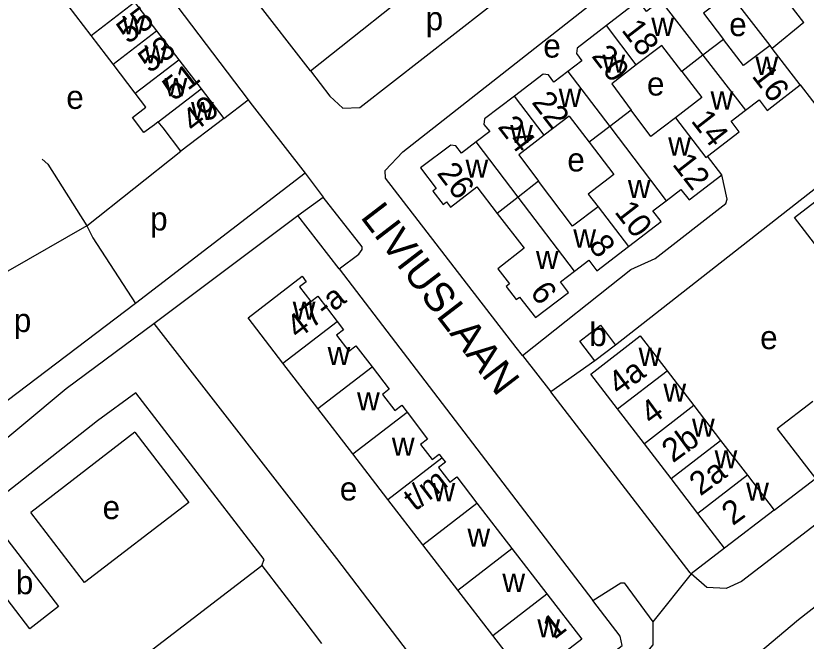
# Model space of a CAD drawing. Extents: x 158848 to 160613, y 385889 to 387762.
# Drawn here: x 159871.5 to 160005.9, y 386555.9 to 386662.2 of the extents above; entities that cross this region are included whole.
import ezdxf

# ---------------------------------------------------------------- set-up
doc = ezdxf.new("R2010")
doc.units = 0
for name, color, linetype in [('BLT_Basislijn', 7, 'Continuous'), ('BLT_Bebouwing', 7, 'Continuous'), ('BLT_Centroide', 7, 'Continuous'), ('BLT_Huisnummer', 7, 'Continuous'), ('BLT_Huisnummer_ tussenligend', 7, 'Continuous'), ('BLT_Huisnummer_reeks', 7, 'Continuous'), ('BLT_Onderverdeling_panden', 7, 'Continuous'), ('BLT_Straatnaam', 7, 'Continuous'), ('BLT_Vlakafsluiter', 7, 'Continuous')]:
    doc.layers.add(name, color=color, linetype=linetype)

msp = doc.modelspace()

# ---------------------------------------------------------------- linework, layer by layer
at = {"layer": 'BLT_Basislijn'}
for p, q in [((159884.03, 386683.48), (159911, 386647.86)), ((160005.44, 386661.04), (159990.37, 386680.7)), ((159921.59, 386652.82), (159906.39, 386672.41)), ((159999.71, 386657.09), (159992.86, 386666.02)), ((160005.44, 386661.04), (160000.09, 386656.59)), ((160004.85, 386650.41), (160014.24, 386638.14)), ((159906.88, 386644.73), (159911, 386647.86)), ((159883.58, 386626.46), (159899.58, 386639.13)), ((159920.72, 386635.41), (159891.89, 386613.25)), ((159920.72, 386635.41), (159923.79, 386631.33)), ((159919.47, 386628.21), (159923.79, 386631.33)), ((159895, 386609.89), (159919.47, 386628.21)), ((159926.49, 386619.16), (159919.47, 386628.21)), ((159883.58, 386626.46), (159870.14, 386618.76)), ((159926.49, 386619.16), (159969.61, 386562.76)), ((159891.89, 386613.25), (159865.31, 386593.16)), ((159957.66, 386604.4), (159962.44, 386598.28)), ((159891.74, 386591.41), (159874.1, 386577.74)), ((159891.74, 386591.41), (159900.93, 386579.45)), ((160000.42, 386578.15), (160007.45, 386583.53)), ((159900.93, 386579.45), (159883.22, 386565.85)), ((159883.22, 386565.85), (159874.1, 386577.74)), ((159992, 386571.67), (159986.32, 386567.3))]:
    msp.add_line(p, q, dxfattribs=at)
for points in [[(159921.59, 386652.82), (159942.74, 386669.61), (159958.92, 386681.91)], [(159921.59, 386652.82), (159924.88, 386648.51), (159927.11, 386646.48), (159929.97, 386646.58), (159962.27, 386671.77), (159963.06, 386672.72), (159963.34, 386675), (159963.14, 386675.85), (159961.74, 386678.2), (159958.92, 386681.91)], [(159957.66, 386604.4), (159956.57, 386605.79), (159953.09, 386610.25), (159934.35, 386634.59), (159934.32, 386635.86), (159937.29, 386639.04), (159985.85, 386677.21), (159990.37, 386680.7)], [(159911, 386647.86), (159911.3, 386647.47), (159920.72, 386635.41)], [(159876.02, 386637.8), (159876.95, 386636.94), (159883.58, 386626.46)], [(160014.24, 386638.14), (159973.45, 386606.21)], [(159957.66, 386604.4), (159976.06, 386619.05), (159980.18, 386620.91), (159992.19, 386630.25), (159992.43, 386630.99), (159991.54, 386635.15)], [(159926.49, 386619.16), (159929.8, 386621.67), (159930.39, 386622.43), (159930.39, 386622.91), (159923.79, 386631.33)], [(159883.58, 386626.46), (159884.61, 386624.45), (159891.89, 386613.25)], [(160072, 386625.2), (159994.85, 386566.02), (159992.27, 386564.83), (159988.99, 386564.97), (159986.32, 386567.3)], [(159816.01, 386559.58), (159856.57, 386580.44), (159864.97, 386586.23), (159880.09, 386598.8), (159895, 386609.89)], [(159895, 386609.89), (159926.03, 386569.94), (159951.15, 386537.01)], [(159969.95, 386603.52), (159962.44, 386598.28)], [(159913.33, 386568.72), (159913.75, 386569.78), (159891.93, 386598.06), (159885.42, 386593.32), (159833.17, 386552.18), (159833.33, 386550.75), (159852.66, 386513.61), (159854.09, 386514), (159867.93, 386521.11)], [(159986.32, 386567.3), (159986.12, 386567.48), (159962.44, 386598.28)], [(160049.48, 386583.96), (160045.31, 386588.46), (160043.15, 386588.7), (160039.17, 386586.55), (160004.57, 386559.51), (159997.74, 386553.78), (159997.8, 386551.51), (160003.17, 386544.41)], [(159969.61, 386562.76), (159974.36, 386565.79), (159974.9, 386565.77), (159979.77, 386559.18)], [(159951.15, 386537.01), (159974.56, 386555.12), (159974.26, 386556.7), (159969.61, 386562.76)], [(159979.77, 386559.18), (159979.77, 386555.27), (159977.95, 386553.04), (159925.28, 386512.85), (159863.76, 386464.98), (159852.68, 386456.75)]]:
    msp.add_lwpolyline(points, dxfattribs=at)
at = {"layer": 'BLT_Bebouwing'}
for p, q in [((159891.71, 386664.5), (159895.45, 386659.62)), ((159895.45, 386659.62), (159899.23, 386654.69)), ((160000.09, 386656.59), (159999.71, 386657.09)), ((160004.85, 386650.41), (160000.09, 386656.59)), ((159899.23, 386654.69), (159903.02, 386649.75)), ((159903.02, 386649.75), (159906.88, 386644.73)), ((159906.88, 386644.73), (159899.58, 386639.13)), ((159965.6, 386645.08), (159961.35, 386641.85)), ((159965.6, 386645.08), (159968.97, 386640.66)), ((159991.54, 386635.15), (159989.1, 386638.31)), ((159973.45, 386606.21), (159969.95, 386603.52)), ((159922.88, 386595.41), (159916.93, 386603.13)), ((159982.21, 386601.82), (159986.77, 386595.91)), ((159928.82, 386587.7), (159922.88, 386595.41)), ((159978.35, 386589.43), (159973.79, 386595.34)), ((159986.77, 386595.91), (159991.32, 386589.99)), ((159982.9, 386583.51), (159978.35, 386589.43)), ((159991.32, 386589.99), (159995.87, 386584.07)), ((159934.76, 386579.98), (159928.82, 386587.7)), ((159987.45, 386577.59), (159982.9, 386583.51)), ((159940.71, 386572.27), (159934.76, 386579.98)), ((159949.9, 386579.35), (159955.85, 386571.64)), ((159946.65, 386564.55), (159940.71, 386572.27)), ((159955.85, 386571.64), (159961.79, 386563.92)), ((159888.9, 386550.01), (159913.33, 386568.72)), ((159952.59, 386556.84), (159946.65, 386564.55))]:
    msp.add_line(p, q, dxfattribs=at)
for points in [[(159992.86, 386666.02), (159988.38, 386662.59), (159991.78, 386658.14)], [(159981.09, 386664.77), (159978.7, 386662.91), (159977.74, 386664.17), (159976.87, 386664.31), (159971.94, 386660.54)], [(159884.34, 386658.84), (159880.42, 386663.94)], [(159971.94, 386660.54), (159966.92, 386656.69), (159966.82, 386655.75), (159967.75, 386654.51), (159965.37, 386652.7)], [(159888.07, 386653.95), (159886.96, 386655.43), (159884.34, 386658.84)], [(159999.71, 386657.09), (159995.19, 386653.69), (159991.78, 386658.14)], [(159984.7, 386652.71), (159981.3, 386657.13), (159976.99, 386653.81)], [(159891.83, 386649.01), (159888.07, 386653.95)], [(159976.99, 386653.81), (159972.84, 386650.61), (159976.09, 386646.1)], [(159965.37, 386652.7), (159962.98, 386650.88), (159962.05, 386652.11), (159961.15, 386652.27), (159956.26, 386648.53)], [(159984.7, 386652.71), (159988.12, 386648.26), (159983.66, 386644.84)], [(159995.56, 386646.12), (159997.85, 386647.88), (159999.23, 386646.09), (160000, 386646.68), (160004.85, 386650.41)], [(159895.73, 386644.16), (159895.08, 386643.66), (159893.3, 386642.32), (159891.33, 386644.88), (159893.64, 386646.65), (159891.83, 386649.01)], [(159956.26, 386648.53), (159951.17, 386644.64), (159951.09, 386643.7), (159952.07, 386642.49), (159949.74, 386640.72)], [(159983.66, 386644.84), (159979.47, 386641.63), (159976.09, 386646.1)], [(159989.1, 386638.31), (159994.47, 386642.43), (159993.09, 386644.23), (159995.56, 386646.12)], [(159899.58, 386639.13), (159896.54, 386643.1), (159895.73, 386644.16)], [(159961.35, 386641.85), (159957.04, 386638.56), (159960.35, 386634.04)], [(159949.74, 386640.72), (159947.26, 386638.84), (159946.33, 386640.05), (159945.46, 386640.17), (159940.29, 386636.3), (159942.97, 386632.8), (159942.43, 386632.37), (159944.15, 386630.11), (159944.7, 386630.55), (159945.4, 386629.64), (159949.89, 386633.07), (159953.35, 386628.59)], [(159968.97, 386640.66), (159973.15, 386635.2), (159968.8, 386631.86), (159970.48, 386629.71)], [(159982.08, 386630.74), (159984.57, 386632.65), (159985.95, 386630.86), (159991.54, 386635.15)], [(159970.48, 386629.71), (159966.15, 386626.39), (159960.35, 386634.04)], [(160008.4, 386621.97), (160003.86, 386627.86), (160012.27, 386634.36), (160016.82, 386628.44)], [(159975.66, 386622.95), (159981.19, 386627.2), (159979.81, 386628.99), (159982.08, 386630.74)], [(159953.34, 386628.59), (159957.95, 386622.65), (159953.45, 386619.16), (159955.43, 386616.61), (159954.86, 386616.18), (159956.59, 386613.93), (159957.15, 386614.36), (159959.85, 386610.86), (159965.48, 386615.15), (159964.11, 386616.95), (159966.5, 386618.78)], [(159966.5, 386618.78), (159968.9, 386620.61), (159970.27, 386618.81), (159975.66, 386622.95)], [(159916.93, 386603.13), (159910.99, 386610.85), (159920.17, 386617.9), (159920.88, 386616.97), (159919.74, 386616.09), (159921.67, 386613.58), (159922.86, 386614.49), (159926.14, 386610.22)], [(159926.14, 386610.22), (159927.22, 386608.81), (159926.04, 386607.9), (159928.14, 386605.17), (159929.33, 386606.09), (159932.08, 386602.5)], [(159969.95, 386603.52), (159967.39, 386606.88), (159970.89, 386609.56), (159973.45, 386606.21)], [(159973.79, 386595.34), (159969.24, 386601.26), (159977.65, 386607.75), (159982.21, 386601.82)], [(159932.08, 386602.5), (159934.99, 386598.71), (159933.83, 386597.82), (159935.94, 386595.07), (159937.11, 386595.96), (159938.02, 386594.78)], [(160007, 386596.63), (160000.95, 386591.95), (160007.45, 386583.53)], [(159938.02, 386594.78), (159941.52, 386590.23), (159940.33, 386589.31), (159942.29, 386586.76), (159943.47, 386587.67), (159943.95, 386587.06)], [(159943.95, 386587.06), (159944.53, 386586.3), (159943.37, 386585.4), (159945.3, 386582.88), (159946.48, 386583.79), (159949.9, 386579.35)], [(159995.87, 386584.07), (160000.42, 386578.15)], [(159992, 386571.67), (159987.45, 386577.59)], [(160000.42, 386578.15), (159992, 386571.67)], [(159913.33, 386568.72), (159920.46, 386559.42), (159923.5, 386555.45)], [(159961.79, 386563.92), (159967.74, 386556.2), (159958.53, 386549.12), (159952.59, 386556.84)]]:
    msp.add_lwpolyline(points, dxfattribs=at)
msp.add_lwpolyline([(159864.51, 386570.2), (159869.43, 386573.97), (159878.8, 386561.75), (159873.88, 386557.98)], close=True, dxfattribs=at)
at = {"layer": 'BLT_Onderverdeling_panden'}
for p, q in [((159884.34, 386658.84), (159891.71, 386664.5)), ((159981.09, 386664.77), (159988.3, 386655.47)), ((159976.99, 386653.81), (159971.94, 386660.54)), ((159888.07, 386653.95), (159895.45, 386659.62)), ((159991.78, 386658.14), (159988.3, 386655.47)), ((159988.3, 386655.47), (159984.7, 386652.71)), ((159988.3, 386655.47), (159995.56, 386646.12)), ((159891.83, 386649.01), (159899.23, 386654.69)), ((159965.37, 386652.7), (159972.49, 386643.34)), ((159895.73, 386644.16), (159903.02, 386649.75)), ((159961.35, 386641.85), (159956.26, 386648.53)), ((159976.09, 386646.1), (159972.49, 386643.34)), ((159972.49, 386643.34), (159968.97, 386640.66)), ((159972.49, 386643.34), (159982.08, 386630.74)), ((159956.89, 386631.35), (159949.74, 386640.72)), ((159960.35, 386634.04), (159956.89, 386631.35)), ((159956.89, 386631.35), (159953.35, 386628.59)), ((159966.5, 386618.78), (159956.89, 386631.35)), ((159970.48, 386629.71), (159975.66, 386622.95)), ((159916.93, 386603.13), (159926.14, 386610.22)), ((159922.88, 386595.41), (159932.08, 386602.5)), ((159973.79, 386595.34), (159982.21, 386601.82)), ((159928.82, 386587.7), (159938.02, 386594.78)), ((159986.77, 386595.91), (159978.35, 386589.43)), ((159982.9, 386583.51), (159991.32, 386589.99)), ((159934.76, 386579.98), (159943.95, 386587.06)), ((159995.87, 386584.07), (159987.45, 386577.59)), ((159940.71, 386572.27), (159949.9, 386579.35)), ((159946.65, 386564.55), (159955.85, 386571.64)), ((159952.59, 386556.84), (159961.79, 386563.92))]:
    msp.add_line(p, q, dxfattribs=at)
msp.add_lwpolyline([(159983.66, 386644.84), (159988.82, 386638.1), (159989.1, 386638.31)], dxfattribs=at)
at = {"layer": 'BLT_Vlakafsluiter'}
msp.add_line((159986.32, 386567.3), (159979.77, 386559.18), dxfattribs=at)

# ---------------------------------------------------------------- texts
at = {"layer": 'BLT_Centroide'}
for s, p in [('w', (159889.63, 386659.03)), ('p', (159941.18, 386659.71)), ('w', (159979.54, 386658.75)), ('e', (159992.77, 386658.71)), ('e', (159961.17, 386655.06)), ('w', (159893.37, 386654.09)), ('w', (159971.22, 386652.5)), ('w', (159997.23, 386652.12)), ('w', (159896.81, 386648.5)), ('e', (159978.8, 386648.61)), ('w', (159963.8, 386646.69)), ('e', (159880.1, 386646.34)), ('w', (159989.61, 386646.23)), ('w', (159901.3, 386644.44)), ('w', (159955.55, 386640.55)), ('w', (159982.41, 386638.41)), ('w', (159947.96, 386634.66)), ('e', (159965.26, 386635.71)), ('w', (159975.55, 386631.2)), ('p', (159894.35, 386625.68)), ('w', (159966.28, 386622.78)), ('w', (159959.92, 386619.14)), ('w', (159918.59, 386610.5)), ('p', (159871.18, 386608.42)), ('b', (159969, 386606.03)), ('e', (159998.03, 386605.5)), ('w', (159924.51, 386602.81)), ('w', (159977.38, 386602.67)), ('w', (159981.59, 386596.58)), ('w', (159929.52, 386595.09)), ('w', (159986.45, 386590.63)), ('w', (159935.44, 386587.38)), ('w', (159990.29, 386585.26)), ('e', (159926.59, 386579.79)), ('w', (159942.34, 386579.66)), ('w', (159995.66, 386579.74)), ('e', (159886.27, 386576.62)), ('w', (159948.28, 386571.94)), ('b', (159871.52, 386563.86)), ('w', (159954.22, 386564.25)), ('w', (159960.16, 386556.53))]:
    msp.add_text(s, height=4, dxfattribs=at).set_placement(p)
at = {"layer": 'BLT_Huisnummer'}
for s, rotation, p in [('53', 37.4945, (159894.29, 386652.29)), ('20', 307.6026, (159969.26, 386655.29)), ('16', 307.5238, (159996.49, 386651.91)), ('49', 37.4945, (159901.72, 386642.16)), ('26', 307.4758, (159942.97, 386635.38)), ('10', 307.8428, (159973.16, 386628.82)), ('6', 307.8428, (159958.79, 386615.1)), ('4a', 36.2399, (159974.06, 386597.51)), ('4', 36.2399, (159979.55, 386592.47)), ('2b', 36.2399, (159983.2, 386586.08)), ('2a', 36.2399, (159987.87, 386580.44)), ('2', 36.2399, (159993.38, 386575.41))]:
    msp.add_text(s, height=4, rotation=rotation, dxfattribs=at).set_placement(p)
at = {"layer": 'BLT_Huisnummer_ tussenligend'}
for s, rotation, p in [('55', 37.4945, (159890.61, 386657.25)), ('18', 307.6026, (159974.34, 386659.72)), ('51', 37.4945, (159898.4, 386647.56)), ('22', 307.6026, (159959.09, 386647.43)), ('14', 307.8428, (159986.16, 386644.28)), ('24', 307.6026, (159953.31, 386643.27)), ('12', 307.8428, (159982.98, 386636.91)), ('8', 307.8428, (159968.72, 386623.07))]:
    msp.add_text(s, height=4, rotation=rotation, dxfattribs=at).set_placement(p)
at = {"layer": 'BLT_Huisnummer_reeks'}
for s, rotation, p in [('47-a', 37.6044, (159919.46, 386607.1)), ('t/m', 37.6023, (159939.37, 386577.83)), ('1', 37.5617, (159963.04, 386556.04))]:
    msp.add_text(s, height=4, rotation=rotation, dxfattribs=at).set_placement(p)
at = {"layer": 'BLT_Straatnaam'}
msp.add_text('LIVIUSLAAN', height=5, rotation=307.4893, dxfattribs=at).set_placement((159929.97, 386627.94))

doc.saveas('drawing.dxf')
